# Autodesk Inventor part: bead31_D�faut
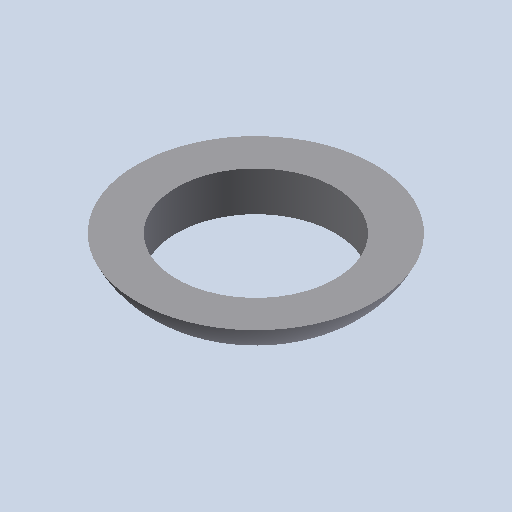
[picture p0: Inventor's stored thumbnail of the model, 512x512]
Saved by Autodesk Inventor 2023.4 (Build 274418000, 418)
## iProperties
Created: 2011-01
Part Number: bead31_D�faut
Document SubType Name: Modeling
Designer: eric
Density: 1 g/cm^3
Mass: 0.0737663 g
Surface Area: 2.05598 cm^2
Volume: 0.0737663 cm^3
Material: Générique
Appearance: Par défaut
Author: eric
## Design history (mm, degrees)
feature "Base1"
node "Corps solides"
node "Corps surfaciques"
node "Solide1"
